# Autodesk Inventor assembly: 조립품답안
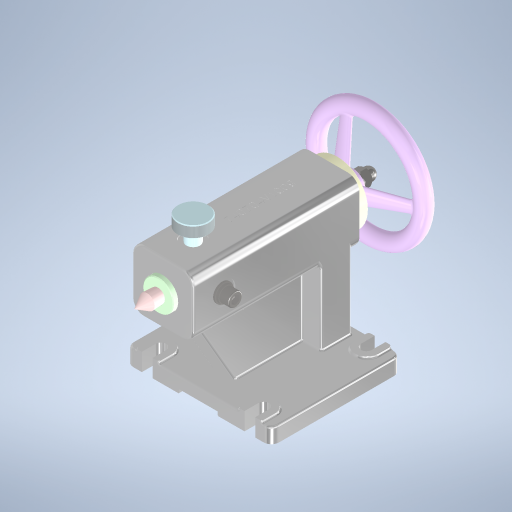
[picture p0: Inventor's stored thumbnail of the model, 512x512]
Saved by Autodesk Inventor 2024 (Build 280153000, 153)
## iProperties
Created: 2024-07
Part Number: 조립품답안
Document SubType Name: Assembly
Designer: com
Author: com
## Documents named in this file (15)
- C:\Users\com\Desktop\740704V1009\조립품답안.iam
- C:\Users\com\Desktop\740704V1009\본체.ipt
- C:\Users\com\Desktop\740704V1009\부시\부시.ipt
- C:\Users\com\Desktop\740704V1009\스러스트 볼 베어링 51101\스러스트 볼 베어링 51101.ipt
- C:\Users\com\Desktop\740704V1009\나사축\나사축.ipt
- C:\Users\com\Desktop\740704V1009\평행키 4x4x14\평행키 4x4x14.ipt
- C:\Users\com\Desktop\740704V1009\핸들\핸들.ipt
- C:\Users\com\Desktop\740704V1009\평와셔 M12\평와셔 M12.ipt
- C:\Users\com\Desktop\740704V1009\스프링  와셔 M12\스프링  와셔 M12.ipt
- C:\Users\com\Desktop\740704V1009\캡너트 M12\캡너트 M12.ipt
- C:\Users\com\Desktop\740704V1009\슬리브\슬리브.ipt
- C:\Users\com\Desktop\740704V1009\육각 소켓 머리 볼트 M6x12\육각 소켓 머리 볼트 M6x12.ipt
- C:\Users\com\Desktop\740704V1009\스톱퍼\스톱퍼.ipt
- C:\Users\com\Desktop\740704V1009\센터\센터.ipt
- C:\Users\com\Desktop\740704V1009\육각 소켓 머리 볼트 M12x16\육각 소켓 머리 볼트 M12x16.ipt
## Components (1 placed, 1 different names)
1. 핸들:1 — 플러쉬:1
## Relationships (1: Flush 1)
- 플러쉬:1 [Flush]: 핸들:1
